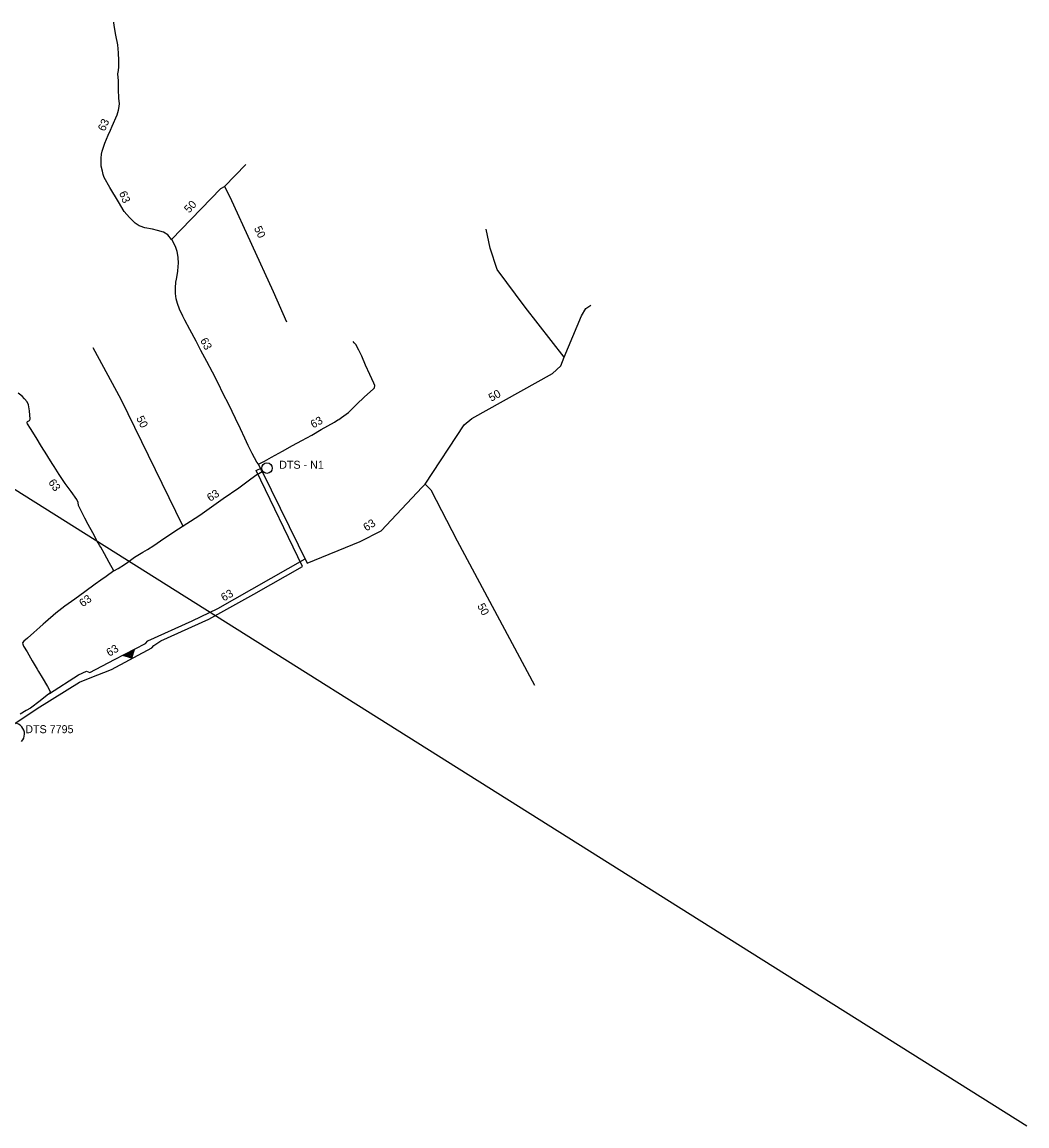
# Model space of a CAD drawing. Extents: x -444817 to -434929, y -1145681 to -1129851.
# Drawn here: x -441954 to -440949, y -1130954 to -1129851 of the extents above; entities that cross this region are included whole.
import ezdxf

# ---------------------------------------------------------------- set-up
doc = ezdxf.new("R2010")
doc.units = 0
for name, color, linetype in [('Vrstva 13', 7, 'Continuous'), ('Vrstva 15', 7, 'Continuous'), ('Vrstva 18', 7, 'Continuous'), ('Vrstva 19', 7, 'Continuous'), ('Vrstva 21', 7, 'Continuous'), ('Vrstva 27', 7, 'Continuous'), ('Vrstva 30', 7, 'Continuous'), ('Vrstva 35', 7, 'Continuous'), ('Vrstva 38', 7, 'Continuous'), ('Vrstva 59', 7, 'Continuous')]:
    doc.layers.add(name, color=color, linetype=linetype)

msp = doc.modelspace()

# ---------------------------------------------------------------- linework, layer by layer
at = {"layer": 'Vrstva 15'}
msp.add_arc((-441962.3, -1130562.6), 11.1, 317.5026, 124.9076, dxfattribs=at)
at = {"layer": 'Vrstva 18'}
msp.add_lwpolyline([(-441975.8, -1130573.8), (-441973.7, -1130560.8), (-441938.5, -1130537.1), (-441896.3, -1130510.6), (-441885.4, -1130506.4), (-441864.4, -1130498), (-441823.8, -1130476.3), (-441821.8, -1130474), (-441814.8, -1130469.5), (-441767, -1130447.9), (-441722, -1130422.7), (-441673.3, -1130395.2), (-441719.6, -1130299.3), (-441714, -1130296.4)], dxfattribs=at)
for points in [[(-441852.6, -1130484.1), (-441841.5, -1130478.3), (-441844.1, -1130486.8)], [(-441850.8, -1130484), (-441842.6, -1130479.7), (-441844.6, -1130485.9)], [(-441849, -1130483.8), (-441843.8, -1130481.1), (-441845, -1130485)], [(-441847.2, -1130483.6), (-441845, -1130482.5), (-441845.5, -1130484.1)]]:
    msp.add_lwpolyline(points, close=True, dxfattribs=at)
at = {"layer": 'Vrstva 19'}
msp.add_circle((-441708.8, -1130296.8), 5.25, dxfattribs=at)
at = {"layer": 'Vrstva 27'}
for points in [[(-441873.3, -1130000), (-441874.5, -1129995), (-441874.6, -1129986.8), (-441874.3, -1129982.8), (-441873.6, -1129979.9), (-441870.9, -1129972.1), (-441867.6, -1129964), (-441865.3, -1129958.8), (-441863.5, -1129955), (-441858.5, -1129943.6), (-441857.1, -1129938.8), (-441856.5, -1129935.4), (-441856.3, -1129932.3), (-441857, -1129927.2), (-441857.2, -1129918.1), (-441857.3, -1129909.5), (-441857.8, -1129902.5), (-441857.4, -1129899.2), (-441856.8, -1129895.6), (-441856.8, -1129889.4), (-441857.1, -1129881.5), (-441858, -1129873.7), (-441859.8, -1129863.9), (-441861.2, -1129856.2), (-441861.8, -1129851.8), (-441862, -1129850.9)], [(-441717.3, -1130292.9), (-441719, -1130290.8), (-441723.5, -1130282.2), (-441727.5, -1130274), (-441731, -1130266.9), (-441735.2, -1130257.6), (-441740.3, -1130247.3), (-441747.1, -1130233.2), (-441752.5, -1130222.4), (-441757.7, -1130211.7), (-441763.2, -1130200.7), (-441768.9, -1130190.3), (-441774.9, -1130179.1), (-441779.7, -1130170), (-441786, -1130158.1), (-441791, -1130148.8), (-441792.8, -1130144.9), (-441796.2, -1130137.8), (-441798.4, -1130132.1), (-441799.7, -1130127.4), (-441800.4, -1130122.1), (-441800.3, -1130116.5), (-441800, -1130110.9), (-441799.3, -1130107.9), (-441798, -1130100.2), (-441797.6, -1130094.8), (-441797.4, -1130092.2), (-441797.5, -1130085.9), (-441798.6, -1130080.1), (-441799.8, -1130076.3), (-441803.5, -1130068.7), (-441804.1, -1130068.1), (-441807.9, -1130063.7), (-441812.3, -1130061), (-441818.2, -1130059.2), (-441823.2, -1130057.9), (-441830.9, -1130056.5), (-441835.7, -1130054.9), (-441836.5, -1130054.7), (-441840.6, -1130052), (-441846.3, -1130046.4), (-441851.5, -1130040.4), (-441857.4, -1130030.6), (-441865.9, -1130016.2), (-441871.5, -1130006.3), (-441872.6, -1130003.3), (-441873.3, -1130000)], [(-441637.9, -1130248.6), (-441637.1, -1130248), (-441634.3, -1130246.1), (-441627.3, -1130241.1), (-441619.2, -1130233.2), (-441611.2, -1130225.4), (-441602.6, -1130217.9), (-441601.3, -1130216.4), (-441601, -1130214.3), (-441601.9, -1130211.8), (-441606, -1130203.1), (-441610.2, -1130193.7), (-441614.1, -1130185), (-441617.1, -1130178.9), (-441620.1, -1130173.3), (-441621.7, -1130171.4), (-441622.7, -1130170.2)], [(-441875, -1130375.9), (-441875.9, -1130374.4), (-441877.5, -1130371.5), (-441878.2, -1130370.4), (-441883, -1130361.4), (-441887.5, -1130353.1), (-441890.8, -1130346.7), (-441897.2, -1130334.2), (-441897.6, -1130331), (-441899, -1130328), (-441904.7, -1130320.1), (-441910.4, -1130312.1), (-441916.7, -1130303.1), (-441921.5, -1130295.3), (-441923, -1130293.1), (-441926.9, -1130286.8), (-441929, -1130283.4), (-441934.3, -1130275), (-441939.7, -1130266.2), (-441945.1, -1130257.3), (-441948.3, -1130252.4), (-441948.6, -1130251.5), (-441948.7, -1130250.7), (-441948.3, -1130250.1), (-441946.2, -1130249.1), (-441945.8, -1130248.6), (-441945.6, -1130247.8), (-441946.2, -1130239.5), (-441947.3, -1130233.6), (-441948.7, -1130230.5), (-441951.1, -1130227.5), (-441953.5, -1130224.9), (-441957.7, -1130221.8)], [(-441717.3, -1130292.9), (-441711.4, -1130289.9), (-441704.4, -1130285.9), (-441693.3, -1130279.9), (-441683.4, -1130274.1), (-441674, -1130269.1), (-441664.1, -1130263.7), (-441654.6, -1130258.3), (-441641.3, -1130250.9), (-441637.9, -1130248.6)], [(-441861.8, -1130399.4), (-441857.6, -1130397.1), (-441851.4, -1130393), (-441848, -1130390.7), (-441841.1, -1130385.9), (-441832.8, -1130380.8), (-441828.1, -1130378), (-441822, -1130374), (-441811.9, -1130367.2), (-441797.4, -1130357.6), (-441785.4, -1130349.8), (-441776, -1130343.7), (-441764.2, -1130335.4), (-441752.6, -1130327.2), (-441737, -1130316.4), (-441725, -1130307.6), (-441719, -1130303.1), (-441717.1, -1130302.2), (-441713.6, -1130300.3), (-441714.2, -1130299.2), (-441717.3, -1130292.9)], [(-441861.8, -1130399.4), (-441866.5, -1130391.1), (-441871.1, -1130382.6), (-441875, -1130375.9)], [(-441861.8, -1130399.4), (-441869.6, -1130405), (-441875, -1130408.8)], [(-441875, -1130408.8), (-441880.6, -1130412.9), (-441890.8, -1130420.4), (-441900.9, -1130427.6), (-441910.8, -1130434.7), (-441919.8, -1130441.6), (-441930.1, -1130450.6), (-441932.4, -1130452.6), (-441935.8, -1130455.6), (-441941.9, -1130461), (-441948.3, -1130466.8), (-441951.9, -1130469.8), (-441953.2, -1130471.5), (-441953, -1130472.8), (-441952.3, -1130474.8), (-441948.6, -1130480.4), (-441943.5, -1130489.3), (-441938.5, -1130497.7), (-441937.1, -1130500)], [(-441937.1, -1130500), (-441933.7, -1130505.9), (-441928.3, -1130515), (-441925.7, -1130519.9), (-441925.6, -1130520.9), (-441926.1, -1130521.9), (-441928.5, -1130523.8), (-441935.5, -1130529.3), (-441945.3, -1130536.7), (-441949.4, -1130539), (-441955.4, -1130542.8)]]:
    msp.add_lwpolyline(points, dxfattribs=at)
at = {"layer": 'Vrstva 35'}
for p, q in [((-441751.2, -1130015.4), (-441729.8, -1129993.3)), ((-441713.6, -1130300.3), (-441668.7, -1130391.9))]:
    msp.add_line(p, q, dxfattribs=at)
for points in [[(-441804.1, -1130068.1), (-441755, -1130017.3), (-441751.2, -1130015.4), (-441745.8, -1130025.6), (-441702.7, -1130120.1), (-441689.3, -1130150.4)], [(-441668.7, -1130391.9), (-441615.6, -1130370.2), (-441594.8, -1130359.4), (-441553.8, -1130315.8), (-441550.8, -1130312.8), (-441511.7, -1130253.6), (-441504, -1130247.1), (-441423.5, -1130202.1), (-441415.2, -1130194.4), (-441411.7, -1130185.8), (-441450.8, -1130136), (-441478.6, -1130098.1), (-441485.7, -1130076.8), (-441489.8, -1130057.9)], [(-441411.7, -1130185.8), (-441394.5, -1130144.5), (-441390.2, -1130137.2), (-441385, -1130133.8)], [(-441792.9, -1130354.6), (-441854.5, -1130228.1), (-441882.4, -1130176.5)], [(-441550.8, -1130312.8), (-441545.1, -1130318.6), (-441518.6, -1130369.5), (-441441.3, -1130513.8)], [(-441861.1, -1130488.1), (-441830.3, -1130471.9), (-441827.8, -1130469.4), (-441783.7, -1130449.5), (-441758.1, -1130437), (-441670.6, -1130387.4)], [(-441926.3, -1130522), (-441897.3, -1130503.3), (-441889.2, -1130499.6), (-441886, -1130500.9), (-441861.1, -1130488.1)]]:
    msp.add_lwpolyline(points, dxfattribs=at)
at = {"layer": 'Vrstva 59'}
msp.add_lwpolyline([(-442473.7, -1129995.8), (-442052.6, -1130260.5), (-441235.6, -1130774.2), (-440949.1, -1130954.3)], dxfattribs=at)

# ---------------------------------------------------------------- texts
at = {"layer": 'Vrstva 13'}
msp.add_text('DTS 7795', height=8, dxfattribs=at).set_placement((-441950.4, -1130561.7))
at = {"layer": 'Vrstva 21'}
msp.add_text('DTS - N1', height=8, dxfattribs=at).set_placement((-441696.6, -1130297.4))
at = {"layer": 'Vrstva 30'}
for rotation, p in [(66.3335, (-441871, -1129960.7)), (292.3508, (-441856.9, -1130021.7)), (297.8282, (-441775.9, -1130169)), (28.8854, (-441662.6, -1130257.2)), (304.8857, (-441927.8, -1130311)), (33.0777, (-441765.6, -1130330.6)), (35.5483, (-441893, -1130436))]:
    msp.add_text('63', height=8, rotation=rotation, dxfattribs=at).set_placement(p)
at = {"layer": 'Vrstva 38'}
for s, rotation, p in [('50', 46.6872, (-441786.7, -1130042.4)), ('50', 295.2532, (-441722, -1130057)), ('50', 29.1975, (-441484.6, -1130230.5)), ('50', 296.2382, (-441839.7, -1130246.8)), ('63', 33.0239, (-441609.4, -1130360.2)), ('63', 29.7467, (-441752, -1130430.2)), ('50', 298.4204, (-441498.9, -1130434.4)), ('63', 31.3903, (-441866.4, -1130485.4))]:
    msp.add_text(s, height=8, rotation=rotation, dxfattribs=at).set_placement(p)

doc.saveas('drawing.dxf')
